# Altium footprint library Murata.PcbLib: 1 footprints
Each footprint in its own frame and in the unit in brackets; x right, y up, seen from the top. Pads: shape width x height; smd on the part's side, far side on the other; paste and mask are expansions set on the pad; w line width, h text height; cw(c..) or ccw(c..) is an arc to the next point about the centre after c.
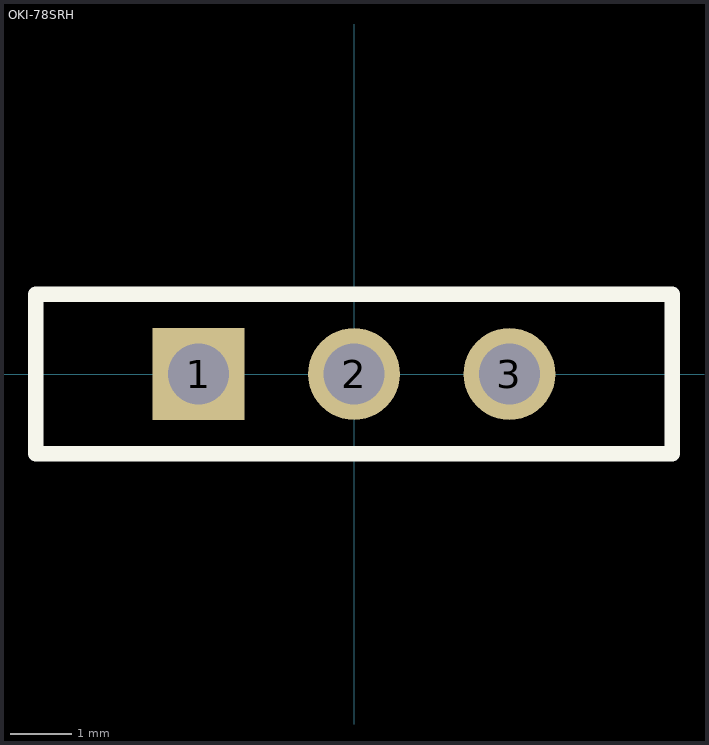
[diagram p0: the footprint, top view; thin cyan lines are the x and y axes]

## OKI-78SRH [mm]
height 7.6
pads (3):
  rect 1.5x1.5 hole 1: 1(-2.54,0)
  round 1.5 hole 1: 2(0,0) 3(2.54,0)
Top Overlay:
  lines w0.254: -5.2,-1.3 5.2,-1.3 5.2,1.3 -5.2,1.3 -5.2,-1.3
3D body: height 10.3, standoff 2.7, extent -5.2,-15.2 5.2,1.3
